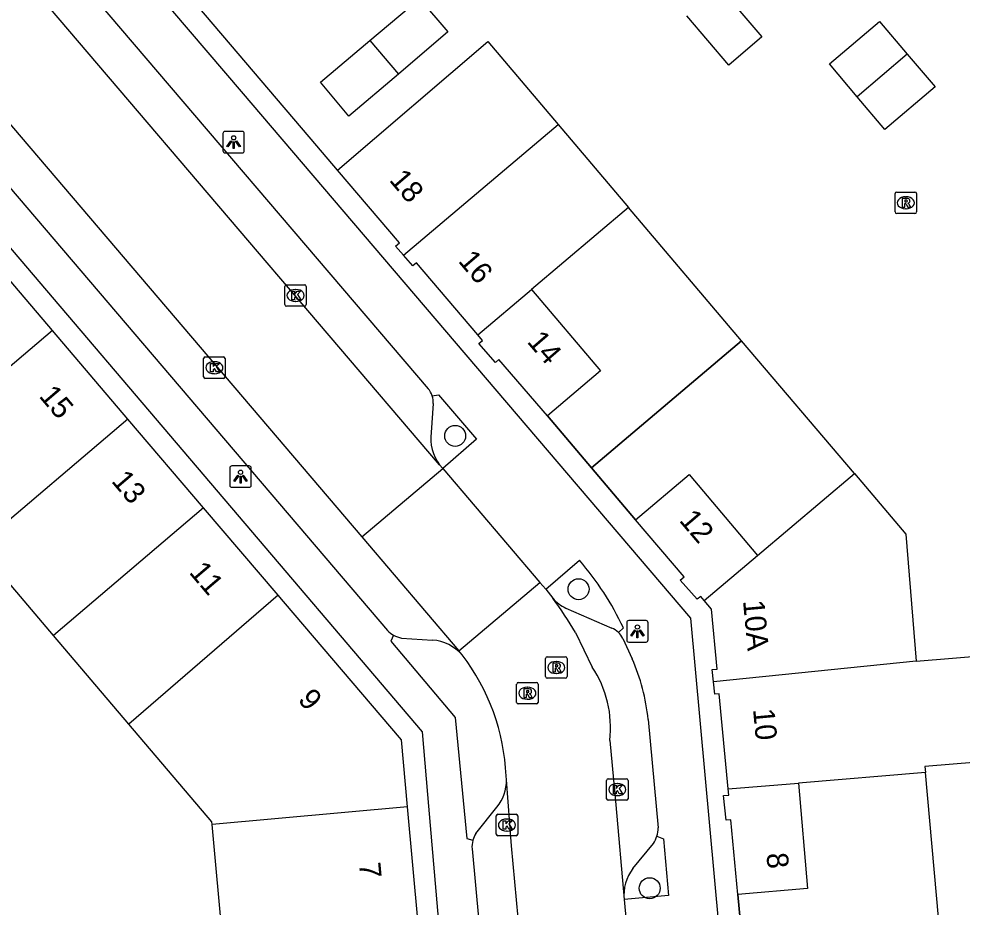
# Model space of a CAD drawing. Extents: x 160379 to 161131, y 383940 to 384849.
# Drawn here: x 160578.08 to 160622.08, y 384539.34 to 384580.77 of the extents above; entities that cross this region are included whole.
import ezdxf

# ---------------------------------------------------------------- set-up
doc = ezdxf.new("R2010")
doc.units = 0
for name, color, linetype in [('IMGEO_Boom', 7, 'Continuous'), ('IMGEO_Erf', 7, 'Continuous'), ('IMGEO_Kolk', 7, 'Continuous'), ('IMGEO_Lichtpunt', 7, 'Continuous'), ('IMGEO_Pand', 7, 'Continuous'), ('IMGEO_Pand_nummerreeks', 7, 'Continuous'), ('IMGEO_Pand_overbouw', 7, 'Continuous'), ('IMGEO_Parkeervlak_open', 7, 'Continuous'), ('IMGEO_Rijbaan_lokaal_open', 7, 'Continuous'), ('IMGEO_Rioolput', 7, 'Continuous'), ('IMGEO_Voetpad_open', 7, 'Continuous')]:
    doc.layers.add(name, color=color, linetype=linetype)

msp = doc.modelspace()

# ---------------------------------------------------------------- linework, layer by layer
at = {"layer": 'IMGEO_Boom'}
for centre in [(160598.433, 384561.32), (160604.19, 384554.17), (160607.508, 384540.221)]:
    msp.add_circle(centre, 0.489, dxfattribs=at)
at = {"layer": 'IMGEO_Erf'}
for points in [[(160592.951, 384573.709), (160591.976, 384574.85), (160586.069, 384581.798)], [(160606.847, 384557.402), (160604.794, 384559.83), (160602.741, 384562.257)], [(160612.221, 384533.608), (160611.92, 384536.772), (160611.62, 384539.935)]]:
    msp.add_lwpolyline(points, dxfattribs=at)
at = {"layer": 'IMGEO_Kolk'}
for p, q in [((160590.486, 384567.444), (160590.486, 384568.296)), ((160590.561, 384568.37), (160591.413, 384568.37)), ((160590.974, 384568.15), (160590.999, 384568.15)), ((160591.487, 384568.296), (160591.487, 384567.444)), ((160590.997, 384567.59), (160590.972, 384567.59)), ((160591.413, 384567.37), (160590.561, 384567.37)), ((160586.698, 384564.077), (160586.698, 384564.929)), ((160586.773, 384565.003), (160587.625, 384565.003)), ((160587.699, 384564.929), (160587.699, 384564.077)), ((160587.186, 384564.783), (160587.211, 384564.783)), ((160587.625, 384564.003), (160586.773, 384564.003)), ((160587.209, 384564.223), (160587.184, 384564.223)), ((160605.498, 384544.398), (160605.498, 384545.25)), ((160605.573, 384545.324), (160606.425, 384545.324)), ((160605.986, 384545.104), (160606.011, 384545.104)), ((160606.499, 384545.25), (160606.499, 384544.398)), ((160606.425, 384544.324), (160605.573, 384544.324)), ((160606.009, 384544.544), (160605.984, 384544.544)), ((160600.349, 384542.743), (160600.349, 384543.595)), ((160600.424, 384543.669), (160601.276, 384543.669)), ((160600.837, 384543.449), (160600.862, 384543.449)), ((160601.35, 384543.595), (160601.35, 384542.743)), ((160600.86, 384542.889), (160600.835, 384542.889)), ((160601.276, 384542.669), (160600.424, 384542.669))]:
    msp.add_line(p, q, dxfattribs=at)
for points in [[(160590.486, 384567.444), (160590.486, 384568.296)], [(160590.561, 384568.37), (160591.413, 384568.37)], [(160590.807, 384568.07), (160590.93, 384568.07), (160590.93, 384567.919), (160591.06, 384568.07), (160591.224, 384568.07), (160591.078, 384567.919), (160591.231, 384567.67), (160591.079, 384567.67), (160590.994, 384567.834), (160590.93, 384567.767), (160590.93, 384567.67), (160590.807, 384567.67), (160590.807, 384568.07)], [(160591.487, 384568.296), (160591.487, 384567.444)], [(160591.413, 384567.37), (160590.561, 384567.37)], [(160586.698, 384564.077), (160586.698, 384564.929)], [(160586.773, 384565.003), (160587.625, 384565.003)], [(160587.699, 384564.929), (160587.699, 384564.077)], [(160587.019, 384564.703), (160587.142, 384564.703), (160587.142, 384564.552), (160587.272, 384564.703), (160587.436, 384564.703), (160587.29, 384564.552), (160587.443, 384564.303), (160587.291, 384564.303), (160587.206, 384564.467), (160587.142, 384564.4), (160587.142, 384564.303), (160587.019, 384564.303), (160587.019, 384564.703)], [(160587.625, 384564.003), (160586.773, 384564.003)], [(160605.498, 384544.398), (160605.498, 384545.25)], [(160605.573, 384545.324), (160606.425, 384545.324)], [(160606.499, 384545.25), (160606.499, 384544.398)], [(160605.819, 384545.024), (160605.942, 384545.024), (160605.942, 384544.873), (160606.072, 384545.024), (160606.236, 384545.024), (160606.09, 384544.873), (160606.243, 384544.624), (160606.091, 384544.624), (160606.006, 384544.788), (160605.942, 384544.721), (160605.942, 384544.624), (160605.819, 384544.624), (160605.819, 384545.024)], [(160606.425, 384544.324), (160605.573, 384544.324)], [(160600.349, 384542.743), (160600.349, 384543.595)], [(160600.424, 384543.669), (160601.276, 384543.669)], [(160600.67, 384543.369), (160600.793, 384543.369), (160600.793, 384543.218), (160600.923, 384543.369), (160601.087, 384543.369), (160600.941, 384543.218), (160601.094, 384542.969), (160600.942, 384542.969), (160600.857, 384543.133), (160600.793, 384543.066), (160600.793, 384542.969), (160600.67, 384542.969), (160600.67, 384543.369)], [(160601.35, 384543.595), (160601.35, 384542.743)], [(160601.276, 384542.669), (160600.424, 384542.669)]]:
    msp.add_lwpolyline(points, dxfattribs=at)
for centre, start, end in [((160590.563, 384568.294), 91.552, 178.448), ((160590.563, 384568.294), 91.552, 178.448), ((160591.411, 384568.294), 1.552, 88.448), ((160591.411, 384568.294), 1.552, 88.448), ((160590.563, 384567.446), 181.552, 268.448), ((160590.563, 384567.446), 181.552, 268.448), ((160591.411, 384567.446), 271.552, 358.448), ((160591.411, 384567.446), 271.552, 358.448), ((160586.775, 384564.927), 91.552, 178.448), ((160586.775, 384564.927), 91.552, 178.448), ((160587.623, 384564.927), 1.552, 88.448), ((160587.623, 384564.927), 1.552, 88.448), ((160586.775, 384564.079), 181.552, 268.448), ((160586.775, 384564.079), 181.552, 268.448), ((160587.623, 384564.079), 271.552, 358.448), ((160587.623, 384564.079), 271.552, 358.448), ((160605.575, 384545.248), 91.552, 178.448), ((160605.575, 384545.248), 91.552, 178.448), ((160606.423, 384545.248), 1.552, 88.448), ((160606.423, 384545.248), 1.552, 88.448), ((160605.575, 384544.4), 181.552, 268.448), ((160605.575, 384544.4), 181.552, 268.448), ((160606.423, 384544.4), 271.552, 358.448), ((160606.423, 384544.4), 271.552, 358.448), ((160600.426, 384543.593), 91.552, 178.448), ((160600.426, 384543.593), 91.552, 178.448), ((160601.274, 384543.593), 1.552, 88.448), ((160601.274, 384543.593), 1.552, 88.448), ((160600.426, 384542.745), 181.552, 268.448), ((160600.426, 384542.745), 181.552, 268.448), ((160601.274, 384542.745), 271.552, 358.448), ((160601.274, 384542.745), 271.552, 358.448)]:
    msp.add_arc(centre, 0.0765, start, end, dxfattribs=at)
for centre, major_axis, ratio, start_param, end_param in [((160590.973, 384567.87), (-0.387, 0.002), 0.722429, 4.712389, 7.853982), ((160590.998, 384567.87), (-0.39, 0.002), 0.717154, 1.570796, 4.712389), ((160587.185, 384564.503), (-0.387, 0.002), 0.722429, 4.712389, 7.853982), ((160587.21, 384564.503), (-0.39, 0.002), 0.717154, 1.570796, 4.712389), ((160605.985, 384544.824), (-0.387, 0.002), 0.722429, 4.712389, 7.853982), ((160606.01, 384544.824), (-0.39, 0.002), 0.717154, 1.570796, 4.712389), ((160600.836, 384543.169), (-0.387, 0.002), 0.722429, 4.712389, 7.853982), ((160600.861, 384543.169), (-0.39, 0.002), 0.717154, 1.570796, 4.712389)]:
    msp.add_ellipse(centre, major_axis=major_axis, ratio=ratio, start_param=start_param, end_param=end_param, dxfattribs=at)
at = {"layer": 'IMGEO_Lichtpunt'}
for p, q in [((160588.502, 384575.521), (160587.694, 384575.521)), ((160588.502, 384575.521), (160587.694, 384575.521)), ((160587.6, 384575.426), (160587.6, 384574.619)), ((160587.6, 384575.426), (160587.6, 384574.619)), ((160588.596, 384574.619), (160588.596, 384575.426)), ((160588.596, 384574.619), (160588.596, 384575.426)), ((160587.694, 384574.525), (160588.502, 384574.525)), ((160587.694, 384574.525), (160588.502, 384574.525)), ((160587.92, 384559.826), (160587.92, 384559.019)), ((160587.92, 384559.826), (160587.92, 384559.019)), ((160588.822, 384559.921), (160588.014, 384559.921)), ((160588.822, 384559.921), (160588.014, 384559.921)), ((160588.916, 384559.019), (160588.916, 384559.826)), ((160588.916, 384559.019), (160588.916, 384559.826)), ((160588.014, 384558.925), (160588.822, 384558.925)), ((160588.014, 384558.925), (160588.822, 384558.925)), ((160606.435, 384552.608), (160606.435, 384551.801)), ((160606.435, 384552.608), (160606.435, 384551.801)), ((160607.337, 384552.703), (160606.529, 384552.703)), ((160607.337, 384552.703), (160606.529, 384552.703)), ((160607.431, 384551.801), (160607.431, 384552.608)), ((160607.431, 384551.801), (160607.431, 384552.608)), ((160606.529, 384551.707), (160607.337, 384551.707)), ((160606.529, 384551.707), (160607.337, 384551.707))]:
    msp.add_line(p, q, dxfattribs=at)
for points in [[(160587.974, 384575.09), (160588.013, 384575.062), (160587.825, 384574.8), (160587.787, 384574.827), (160587.974, 384575.09)], [(160588.076, 384575.042), (160588.123, 384575.042), (160588.123, 384574.72), (160588.076, 384574.72), (160588.076, 384575.042)], [(160588.186, 384575.062), (160588.224, 384575.089), (160588.411, 384574.827), (160588.372, 384574.799), (160588.186, 384575.062)], [(160588.294, 384559.49), (160588.333, 384559.462), (160588.145, 384559.2), (160588.107, 384559.227), (160588.294, 384559.49)], [(160588.396, 384559.442), (160588.443, 384559.442), (160588.443, 384559.12), (160588.396, 384559.12), (160588.396, 384559.442)], [(160588.506, 384559.462), (160588.544, 384559.489), (160588.731, 384559.227), (160588.692, 384559.199), (160588.506, 384559.462)], [(160606.809, 384552.272), (160606.848, 384552.244), (160606.66, 384551.982), (160606.622, 384552.009), (160606.809, 384552.272)], [(160606.911, 384552.224), (160606.958, 384552.224), (160606.958, 384551.902), (160606.911, 384551.902), (160606.911, 384552.224)], [(160607.021, 384552.244), (160607.059, 384552.271), (160607.246, 384552.009), (160607.207, 384551.981), (160607.021, 384552.244)]]:
    msp.add_lwpolyline(points, dxfattribs=at)
for centre in [(160588.099, 384575.224), (160588.419, 384559.624), (160606.934, 384552.406)]:
    msp.add_circle(centre, 0.0994, dxfattribs=at)
for centre, start, end in [((160587.694, 384575.426), 90, 180), ((160587.694, 384575.426), 90, 180), ((160588.502, 384575.426), 0, 90), ((160588.502, 384575.426), 0, 90), ((160587.694, 384574.619), 180, 270), ((160587.694, 384574.619), 180, 270), ((160588.502, 384574.619), 270, 0), ((160588.502, 384574.619), 270, 360), ((160588.014, 384559.826), 90, 180), ((160588.014, 384559.826), 90, 180), ((160588.822, 384559.826), 0, 90), ((160588.822, 384559.826), 0, 90), ((160588.014, 384559.019), 180, 270), ((160588.014, 384559.019), 180, 270), ((160588.822, 384559.019), 270, 0), ((160588.822, 384559.019), 270, 360), ((160606.529, 384552.608), 90, 180), ((160606.529, 384552.608), 90, 180), ((160607.337, 384552.608), 0, 90), ((160607.337, 384552.608), 0, 90), ((160606.529, 384551.801), 180, 270), ((160606.529, 384551.801), 180, 270), ((160607.337, 384551.801), 270, 0), ((160607.337, 384551.801), 270, 360)]:
    msp.add_arc(centre, 0.0946, start, end, dxfattribs=at)
at = {"layer": 'IMGEO_Pand'}
for points in [[(160610.786, 384582.237), (160612.736, 384579.938), (160611.2, 384578.612), (160609.234, 384580.921)], [(160594.453, 384579.764), (160596.764, 384581.719), (160598.093, 384580.163), (160595.786, 384578.199)], [(160617.187, 384577.137), (160615.891, 384578.672), (160618.224, 384580.65), (160619.522, 384579.129)], [(160595.786, 384578.199), (160593.479, 384576.234), (160592.15, 384577.816), (160594.453, 384579.764)], [(160592.951, 384573.709), (160599.959, 384579.718), (160603.236, 384575.843)], [(160594.453, 384579.764), (160595.786, 384578.199)], [(160619.522, 384579.129), (160620.82, 384577.607), (160618.472, 384575.616), (160617.187, 384577.137)], [(160619.522, 384579.129), (160617.187, 384577.137)], [(160596.025, 384569.745), (160603.236, 384575.843)], [(160603.236, 384575.843), (160606.513, 384571.967), (160602, 384568.151)], [(160596.025, 384569.745), (160595.656, 384570.166), (160595.834, 384570.325), (160592.951, 384573.709)], [(160579.646, 384566.239), (160576.125, 384570.373)], [(160599.493, 384566.031), (160596.623, 384569.399), (160596.457, 384569.251), (160596.025, 384569.745)], [(160599.493, 384566.031), (160602, 384568.151)], [(160602, 384568.151), (160605.215, 384564.349), (160602.741, 384562.257)], [(160579.646, 384566.239), (160572.651, 384560.292)], [(160583.167, 384562.105), (160579.646, 384566.239)], [(160602.741, 384562.257), (160600.474, 384564.881), (160600.319, 384564.749), (160599.539, 384565.626), (160599.716, 384565.77), (160599.493, 384566.031)], [(160583.167, 384562.105), (160576.169, 384556.155)], [(160586.688, 384557.971), (160583.167, 384562.105)], [(160606.847, 384557.402), (160609.356, 384559.518), (160612.541, 384555.742)], [(160612.541, 384555.742), (160617.067, 384559.559), (160619.452, 384556.731), (160619.944, 384550.806)], [(160586.688, 384557.971), (160579.687, 384552.018)], [(160590.17, 384553.884), (160586.688, 384557.971)], [(160610.051, 384553.642), (160609.888, 384553.835), (160609.723, 384553.712), (160608.928, 384554.596), (160609.112, 384554.744), (160606.847, 384557.402)], [(160579.687, 384552.018), (160576.169, 384556.155)], [(160610.051, 384553.642), (160612.541, 384555.742)], [(160590.17, 384553.884), (160583.204, 384547.881)], [(160596.213, 384544.024), (160595.926, 384547.149), (160590.421, 384553.589), (160590.17, 384553.884)], [(160610.483, 384549.847), (160610.425, 384550.419), (160610.649, 384550.435), (160610.389, 384553.239), (160610.051, 384553.642)], [(160583.204, 384547.881), (160579.687, 384552.018)], [(160619.944, 384550.806), (160610.483, 384549.847)], [(160619.944, 384550.806), (160623.524, 384551.103), (160623.931, 384546.19), (160620.351, 384545.893), (160620.374, 384545.619), (160614.454, 384545.127)], [(160611.166, 384544.854), (160610.755, 384549.291), (160610.541, 384549.275), (160610.483, 384549.847)], [(160587.092, 384543.187), (160587.079, 384543.324), (160583.204, 384547.881)], [(160611.166, 384544.854), (160614.454, 384545.127)], [(160614.454, 384545.127), (160614.863, 384540.204), (160611.62, 384539.935)], [(160611.62, 384539.935), (160611.298, 384543.415), (160611.074, 384543.394), (160610.956, 384544.546), (160611.193, 384544.564), (160611.166, 384544.854)], [(160596.213, 384544.024), (160587.092, 384543.187)], [(160596.713, 384538.576), (160596.213, 384544.024)], [(160587.591, 384537.739), (160587.092, 384543.187)]]:
    msp.add_lwpolyline(points, dxfattribs=at)
at = {"layer": 'IMGEO_Pand_overbouw'}
for points in [[(160611.798, 384565.753), (160606.513, 384571.967), (160602, 384568.151), (160605.215, 384564.349), (160602.741, 384562.257), (160604.794, 384559.83)], [(160611.798, 384565.753), (160604.794, 384559.83), (160606.847, 384557.402), (160609.356, 384559.518), (160612.541, 384555.742), (160617.067, 384559.559)], [(160611.92, 384536.772), (160621.095, 384537.643), (160620.374, 384545.619), (160614.454, 384545.127), (160614.863, 384540.204), (160611.62, 384539.935)]]:
    msp.add_lwpolyline(points, close=True, dxfattribs=at)
at = {"layer": 'IMGEO_Parkeervlak_open'}
for points in [[(160597.402, 384562.826), (160597.314, 384561.481)], [(160603.598, 384553.281), (160605.735, 384552.358)], [(160595.936, 384551.893), (160597.378, 384551.798)], [(160599.401, 384542.776), (160600.377, 384544.01)], [(160606.72, 384541.139), (160607.689, 384542.308)]]:
    msp.add_lwpolyline(points, dxfattribs=at)
for centre, radius, start, end in [((160596.545, 384562.927), 0.863, 353.2539, 17.7308), ((160599.321, 384561.2), 2.026, 172.0323, 217.3052), ((160604.428, 384555.004), 1.913, 221.0085, 244.271), ((160605.395, 384551.475), 0.946, 45.8579, 68.9444), ((160596.091, 384552.959), 1.077, 240.4283, 261.699), ((160597.181, 384549.664), 2.143, 42.5033, 84.7318), ((160598.959, 384545.224), 1.866, 319.4264, 1.5989), ((160600.303, 384542.178), 1.082, 146.4422, 165.1024), ((160606.462, 384543.078), 1.449, 327.9013, 343.1119), ((160608.448, 384539.87), 2.144, 143.7215, 184.8269)]:
    msp.add_arc(centre, radius, start, end, dxfattribs=at)
at = {"layer": 'IMGEO_Rijbaan_lokaal_open'}
for points in [[(160550.781, 384607.389), (160594.077, 384556.607)], [(160597.709, 384559.972), (160577.091, 384584.122)], [(160594.077, 384556.607), (160597.856, 384559.801)], [(160597.856, 384559.801), (160597.709, 384559.972)], [(160597.856, 384559.801), (160602.383, 384554.478)], [(160594.077, 384556.607), (160598.599, 384551.302)], [(160598.599, 384551.302), (160602.383, 384554.478)], [(160602.383, 384554.478), (160602.661, 384554.175)], [(160602.661, 384554.175), (160602.985, 384553.749)], [(160604.045, 384552.148), (160604.819, 384550.539)], [(160598.761, 384551.112), (160598.599, 384551.302)], [(160605.642, 384547.117), (160605.922, 384544.111), (160606.312, 384539.69)], [(160600.825, 384545.276), (160600.81, 384545.462)], [(160604.629, 384503.073), (160604.636, 384503.37), (160603.161, 384519.524), (160601.069, 384542.207), (160600.825, 384545.276)], [(160606.312, 384539.69), (160606.876, 384533.648)]]:
    msp.add_lwpolyline(points, dxfattribs=at)
for centre, radius, start, end in [((160589.455, 384543.639), 16.89, 30.2495, 36.7665), ((160590.715, 384544.997), 10.106, 2.6349, 37.232), ((160600.687, 384547.735), 4.993, 352.8862, 34.1597)]:
    msp.add_arc(centre, radius, start, end, dxfattribs=at)
at = {"layer": 'IMGEO_Rioolput'}
for p, q in [((160618.956, 384571.769), (160618.956, 384572.621)), ((160619.031, 384572.695), (160619.883, 384572.695)), ((160619.444, 384572.475), (160619.469, 384572.475)), ((160619.957, 384572.621), (160619.957, 384571.769)), ((160619.883, 384571.695), (160619.031, 384571.695)), ((160619.467, 384571.915), (160619.442, 384571.915)), ((160602.652, 384550.091), (160602.652, 384550.943)), ((160602.727, 384551.017), (160603.579, 384551.017)), ((160603.653, 384550.943), (160603.653, 384550.091)), ((160603.14, 384550.797), (160603.165, 384550.797)), ((160603.579, 384550.017), (160602.727, 384550.017)), ((160603.163, 384550.237), (160603.138, 384550.237)), ((160601.302, 384548.892), (160601.302, 384549.744)), ((160601.377, 384549.818), (160602.229, 384549.818)), ((160601.79, 384549.598), (160601.815, 384549.598)), ((160602.303, 384549.744), (160602.303, 384548.892)), ((160602.229, 384548.818), (160601.377, 384548.818)), ((160601.813, 384549.038), (160601.788, 384549.038))]:
    msp.add_line(p, q, dxfattribs=at)
for points in [[(160618.956, 384571.769), (160618.956, 384572.621)], [(160619.031, 384572.695), (160619.883, 384572.695)], [(160619.545, 384572.393), (160619.293, 384572.395), (160619.293, 384571.995)], [(160619.957, 384572.621), (160619.957, 384571.769)], [(160619.293, 384571.995), (160619.417, 384571.995), (160619.417, 384572.157), (160619.428, 384572.157)], [(160619.471, 384572.314), (160619.417, 384572.314), (160619.417, 384572.233)], [(160619.417, 384572.233), (160619.469, 384572.233)], [(160619.475, 384572.128), (160619.546, 384571.995), (160619.686, 384571.995), (160619.621, 384572.121)], [(160619.883, 384571.695), (160619.031, 384571.695)], [(160602.652, 384550.091), (160602.652, 384550.943)], [(160602.727, 384551.017), (160603.579, 384551.017)], [(160603.653, 384550.943), (160603.653, 384550.091)], [(160603.241, 384550.715), (160602.989, 384550.717), (160602.989, 384550.317)], [(160602.989, 384550.317), (160603.113, 384550.317), (160603.113, 384550.479), (160603.124, 384550.479)], [(160603.167, 384550.636), (160603.113, 384550.636), (160603.113, 384550.555)], [(160603.113, 384550.555), (160603.165, 384550.555)], [(160603.171, 384550.45), (160603.242, 384550.317), (160603.382, 384550.317), (160603.317, 384550.443)], [(160603.579, 384550.017), (160602.727, 384550.017)], [(160601.302, 384548.892), (160601.302, 384549.744)], [(160601.377, 384549.818), (160602.229, 384549.818)], [(160601.891, 384549.516), (160601.639, 384549.518), (160601.639, 384549.118)], [(160602.303, 384549.744), (160602.303, 384548.892)], [(160601.639, 384549.118), (160601.763, 384549.118), (160601.763, 384549.28), (160601.774, 384549.28)], [(160601.817, 384549.437), (160601.763, 384549.437), (160601.763, 384549.356)], [(160601.763, 384549.356), (160601.815, 384549.356)], [(160601.821, 384549.251), (160601.892, 384549.118), (160602.032, 384549.118), (160601.967, 384549.244)], [(160602.229, 384548.818), (160601.377, 384548.818)]]:
    msp.add_lwpolyline(points, dxfattribs=at)
for centre, radius, start, end in [((160619.033, 384572.619), 0.0765, 91.552, 178.448), ((160619.033, 384572.619), 0.0765, 91.552, 178.448), ((160619.544, 384572.283), 0.109, 350.3612, 89.416), ((160619.881, 384572.619), 0.0765, 1.552, 88.448), ((160619.881, 384572.619), 0.0765, 1.552, 88.448), ((160619.427, 384572.104), 0.0533, 26.0293, 88.6989), ((160619.453, 384572.422), 0.19, 274.7715, 282.9687), ((160619.477, 384572.218), 0.0964, 77.0061, 93.1865), ((160619.491, 384572.275), 0.0378, 276.6634, 79.6772), ((160619.542, 384572.283), 0.112, 277.5842, 350.9817), ((160619.526, 384572.068), 0.108, 29.5134, 73.7905), ((160619.033, 384571.771), 0.0765, 181.552, 268.448), ((160619.033, 384571.771), 0.0765, 181.552, 268.448), ((160619.881, 384571.771), 0.0765, 271.552, 358.448), ((160619.881, 384571.771), 0.0765, 271.552, 358.448), ((160602.729, 384550.941), 0.0765, 91.552, 178.448), ((160602.729, 384550.941), 0.0765, 91.552, 178.448), ((160603.577, 384550.941), 0.0765, 1.552, 88.448), ((160603.577, 384550.941), 0.0765, 1.552, 88.448), ((160603.123, 384550.426), 0.0533, 26.0293, 88.6989), ((160603.149, 384550.744), 0.19, 274.7715, 282.9687), ((160603.173, 384550.54), 0.0964, 77.0061, 93.1865), ((160603.187, 384550.597), 0.0378, 276.6634, 79.6772), ((160603.24, 384550.605), 0.109, 350.3612, 89.416), ((160603.238, 384550.605), 0.112, 277.5842, 350.9817), ((160603.222, 384550.39), 0.108, 29.5134, 73.7905), ((160602.729, 384550.093), 0.0765, 181.552, 268.448), ((160602.729, 384550.093), 0.0765, 181.552, 268.448), ((160603.577, 384550.093), 0.0765, 271.552, 358.448), ((160603.577, 384550.093), 0.0765, 271.552, 358.448), ((160601.379, 384549.742), 0.0765, 91.552, 178.448), ((160601.379, 384549.742), 0.0765, 91.552, 178.448), ((160601.89, 384549.406), 0.109, 350.3612, 89.416), ((160602.227, 384549.742), 0.0765, 1.552, 88.448), ((160602.227, 384549.742), 0.0765, 1.552, 88.448), ((160601.773, 384549.227), 0.0533, 26.0293, 88.6989), ((160601.799, 384549.545), 0.19, 274.7715, 282.9687), ((160601.823, 384549.341), 0.0964, 77.0061, 93.1865), ((160601.837, 384549.398), 0.0378, 276.6634, 79.6772), ((160601.888, 384549.406), 0.112, 277.5842, 350.9817), ((160601.872, 384549.191), 0.108, 29.5134, 73.7905), ((160601.379, 384548.894), 0.0765, 181.552, 268.448), ((160601.379, 384548.894), 0.0765, 181.552, 268.448), ((160602.227, 384548.894), 0.0765, 271.552, 358.448), ((160602.227, 384548.894), 0.0765, 271.552, 358.448)]:
    msp.add_arc(centre, radius, start, end, dxfattribs=at)
for centre, major_axis, ratio, start_param, end_param in [((160619.443, 384572.195), (-0.387, 0.002), 0.722429, 4.712389, 7.853982), ((160619.468, 384572.195), (-0.39, 0.002), 0.717154, 1.570796, 4.712389), ((160603.139, 384550.517), (-0.387, 0.002), 0.722429, 4.712389, 7.853982), ((160603.164, 384550.517), (-0.39, 0.002), 0.717154, 1.570796, 4.712389), ((160601.789, 384549.318), (-0.387, 0.002), 0.722429, 4.712389, 7.853982), ((160601.814, 384549.318), (-0.39, 0.002), 0.717154, 1.570796, 4.712389)]:
    msp.add_ellipse(centre, major_axis=major_axis, ratio=ratio, start_param=start_param, end_param=end_param, dxfattribs=at)
at = {"layer": 'IMGEO_Voetpad_open'}
for points in [[(160601.299, 384499.323), (160600.989, 384502.935), (160599.078, 384522.405), (160597.158, 384544.586), (160596.904, 384547.52), (160547.519, 384605.522), (160544.872, 384608.601), (160534.548, 384620.664)], [(160549.373, 384606.064), (160595.282, 384552.25)], [(160614.226, 384500.488), (160611.199, 384533.452), (160609.42, 384552.826), (160588.469, 384577.392), (160578.674, 384588.862)], [(160580.542, 384582.995), (160597.17, 384563.523)], [(160597.367, 384563.19), (160597.654, 384563.242), (160599.425, 384561.168), (160597.856, 384559.801)], [(160602.661, 384554.175), (160604.23, 384555.518)], [(160606.282, 384552.363), (160606.054, 384552.154)], [(160595.56, 384552.022), (160595.438, 384551.749), (160598.439, 384548.186), (160598.975, 384542.546), (160599.257, 384542.456)], [(160606.251, 384551.877), (160606.694, 384550.925)], [(160607.438, 384548.088), (160607.909, 384543.036)], [(160607.848, 384542.657), (160608.148, 384542.521), (160608.387, 384539.886), (160606.312, 384539.69)], [(160599.222, 384542.055), (160602.278, 384508.847), (160602.491, 384506.156)]]:
    msp.add_lwpolyline(points, dxfattribs=at)
for centre, radius, start, end in [((160596.538, 384562.925), 0.87, 17.7623, 43.4541), ((160594.019, 384546.632), 13.536, 25.0484, 41.0313), ((160596.072, 384552.93), 1.042, 220.7115, 240.5752), ((160605.38, 384551.466), 0.963, 25.257, 45.5833), ((160597.671, 384547.043), 9.823, 6.1089, 23.2808), ((160606.457, 384543.075), 1.452, 343.2626, 358.4507), ((160600.317, 384542.161), 1.1, 164.474, 185.5496)]:
    msp.add_arc(centre, radius, start, end, dxfattribs=at)

# ---------------------------------------------------------------- texts
at = {"layer": 'IMGEO_Pand_nummerreeks'}
for s, rotation, p in [('18', 310.4277, (160595.321, 384573.24)), ('16', 310.4392, (160598.54, 384569.462)), ('14', 310.823, (160601.752, 384565.697)), ('15', 310.422, (160578.982, 384563.163)), ('13', 310.422, (160582.36, 384559.198)), ('12', 310.4334, (160608.849, 384557.365)), ('11', 310.422, (160585.984, 384554.943)), ('10A', 275.2996, (160611.859, 384553.63)), ('9', 310.5251, (160591.058, 384548.995)), ('10', 275.2939, (160612.328, 384548.567)), ('8', 275.2882, (160612.95, 384541.837)), ('7', 275.2424, (160593.944, 384541.391))]:
    msp.add_text(s, height=1, rotation=rotation, dxfattribs=at).set_placement(p)

doc.saveas('drawing.dxf')
